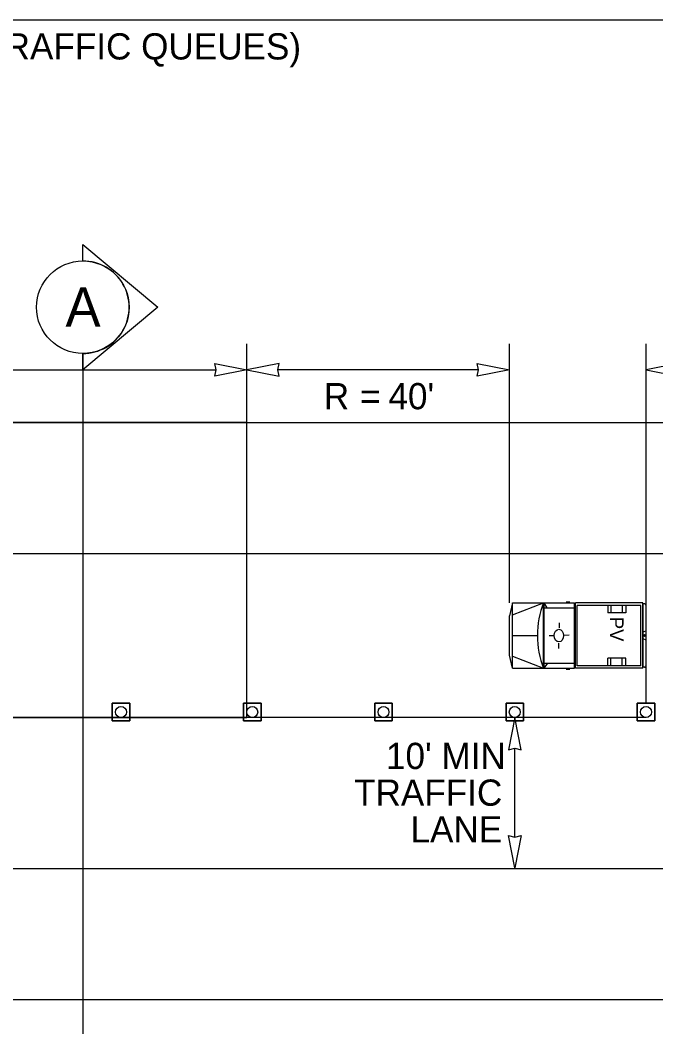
# Model space of a CAD drawing. Extents: x 99999.1 to 100095.7, y 99995 to 100010.7.
# Drawn here: x 100049.243 to 100051.18, y 100005.649 to 100008.719 of the extents above; entities that cross this region are included whole.
import ezdxf

# ---------------------------------------------------------------- set-up
doc = ezdxf.new("R2010")
doc.units = 0
for name, color, linetype in [('RD_ED_ShoulderPavedEdge', 7, 'Continuous'), ('RD_MK_LineEdgeWhite', 7, 'Continuous'), ('RD_MK_LineSkipCenter', 7, 'Continuous'), ('SH_TI_WZSectionCut', 7, 'Continuous'), ('TR_WZ_ProtectiveVehicle', 7, 'Continuous'), ('TR_WZ_TrafficCone', 7, 'Continuous'), ('TR_WZ_WorkZoneDetails', 7, 'Continuous'), ('TR_WZ_WorkZoneTextCurrent', 7, 'Continuous')]:
    doc.layers.add(name, color=color, linetype=linetype)

msp = doc.modelspace()

# ---------------------------------------------------------------- linework, layer by layer
at = {"layer": 'RD_ED_ShoulderPavedEdge'}
for p, q in [((100040.1076, 100007.4923), (100055.6424, 100007.4923)), ((100040.1076, 100005.7323), (100055.6424, 100005.7323))]:
    msp.add_line(p, q, dxfattribs=at)
at = {"layer": 'RD_MK_LineEdgeWhite'}
for p, q in [((100040.1076, 100007.0923), (100055.6424, 100007.0923)), ((100040.1076, 100006.1323), (100055.6424, 100006.1323))]:
    msp.add_line(p, q, dxfattribs=at)
at = {"layer": 'RD_MK_LineSkipCenter'}
msp.add_lwpolyline([(100051.15, 100006.5923), (100043.4767, 100006.5923)], dxfattribs=at)
at = {"layer": 'SH_TI_WZSectionCut'}
for p, q in [((100049.4337, 100007.9847), (100049.4337, 100008.0346)), ((100049.4337, 100008.0346), (100049.6619, 100007.8435)), ((100049.6619, 100007.8435), (100049.4337, 100007.6523)), ((100049.4337, 100007.6523), (100049.4337, 100007.7022)), ((100049.4338, 100007.7022), (100049.4338, 100005.5723))]:
    msp.add_line(p, q, dxfattribs=at)
msp.add_circle((100049.4338, 100007.8435), 0.1412, dxfattribs=at)
msp.add_arc((100049.4338, 100007.8435), 0.1412, 269.9978, 90.0022, dxfattribs=at)
at = {"layer": 'TR_WZ_ProtectiveVehicle'}
for p, q in [((100050.743, 100006.9423), (100050.7338, 100006.902)), ((100050.743, 100006.7423), (100050.743, 100006.9423)), ((100050.743, 100006.9423), (100050.9319, 100006.9423)), ((100050.743, 100006.9057), (100050.8375, 100006.9423)), ((100050.8375, 100006.7423), (100050.8375, 100006.9423)), ((100050.8392, 100006.7423), (100050.8392, 100006.9423)), ((100050.8492, 100006.9268), (100050.8392, 100006.9423)), ((100050.8392, 100006.9268), (100050.9319, 100006.9268)), ((100050.9062, 100006.9451), (100050.9175, 100006.9451)), ((100050.9319, 100006.7423), (100050.9319, 100006.9423)), ((100051.1404, 100006.9423), (100050.9347, 100006.9423)), ((100050.9347, 100006.7423), (100050.9347, 100006.9423)), ((100051.1346, 100006.9344), (100050.9405, 100006.9344)), ((100050.9405, 100006.7503), (100050.9405, 100006.9344)), ((100051.0332, 100006.9344), (100051.0332, 100006.9113)), ((100051.0432, 100006.9344), (100051.0432, 100006.9113)), ((100051.0772, 100006.9344), (100051.0772, 100006.9113)), ((100051.0882, 100006.9344), (100051.0882, 100006.9113)), ((100051.1346, 100006.7503), (100051.1346, 100006.9344)), ((100051.1404, 100006.7423), (100051.1404, 100006.9423)), ((100051.1456, 100006.939), (100051.1411, 100006.939)), ((100051.1411, 100006.7456), (100051.1411, 100006.939)), ((100051.15, 100006.7517), (100051.15, 100006.9329)), ((100050.7338, 100006.7827), (100050.7338, 100006.902)), ((100051.0882, 100006.9113), (100051.0332, 100006.9113)), ((100050.8852, 100006.8808), (100050.885, 100006.8658)), ((100050.743, 100006.8423), (100050.8189, 100006.8423)), ((100050.8544, 100006.8422), (100050.867, 100006.8423)), ((100050.8986, 100006.8427), (100050.8986, 100006.8427)), ((100050.9154, 100006.8431), (100050.9005, 100006.8427)), ((100051.15, 100006.8564), (100051.1411, 100006.8527)), ((100051.15, 100006.8282), (100051.1411, 100006.832)), ((100051.1476, 100006.8423), (100051.1435, 100006.8423)), ((100051.1456, 100006.8395), (100051.1456, 100006.8451)), ((100050.8845, 100006.8027), (100050.8845, 100006.8188)), ((100050.743, 100006.7423), (100050.7338, 100006.7827)), ((100050.743, 100006.779), (100050.8375, 100006.7423)), ((100051.0882, 100006.7733), (100051.0332, 100006.7733)), ((100051.0332, 100006.7503), (100051.0332, 100006.7733)), ((100051.0432, 100006.7503), (100051.0432, 100006.7733)), ((100051.0772, 100006.7503), (100051.0772, 100006.7733)), ((100051.0882, 100006.7503), (100051.0882, 100006.7733)), ((100050.743, 100006.7423), (100050.9319, 100006.7423)), ((100050.8392, 100006.7423), (100050.8512, 100006.7578)), ((100050.8392, 100006.7578), (100050.9319, 100006.7578)), ((100050.9062, 100006.7395), (100050.9175, 100006.7395)), ((100051.1404, 100006.7423), (100050.9347, 100006.7423)), ((100051.1346, 100006.7503), (100050.9405, 100006.7503)), ((100051.1456, 100006.7456), (100051.1411, 100006.7456))]:
    msp.add_line(p, q, dxfattribs=at)
for centre, major_axis, start_param, end_param in [((100050.9725, 100006.8424), (0, -0.2099), 4.215852, 5.209111), ((100051.1456, 100006.9329), (0, 0.0061), 4.712389, 6.283185), ((100051.1456, 100006.7517), (0, -0.0061), 6.283185, 7.853982)]:
    msp.add_ellipse(centre, major_axis=major_axis, ratio=0.73155, start_param=start_param, end_param=end_param, dxfattribs=at)
for centre, major_axis in [((100050.8845, 100006.8423), (0, 0.0193)), ((100051.1456, 100006.8423), (0, 0.00282))]:
    msp.add_ellipse(centre, major_axis=major_axis, ratio=0.73155, dxfattribs=at)
at = {"layer": 'TR_WZ_TrafficCone'}
for points in [[(100049.5234, 100006.6357), (100049.5767, 100006.6357), (100049.5767, 100006.5823), (100049.5234, 100006.5823), (100049.5234, 100006.6357)], [(100049.5234, 100006.5823), (100049.5767, 100006.5823), (100049.5767, 100006.6357), (100049.5234, 100006.6357), (100049.5234, 100006.5823)], [(100049.9234, 100006.6357), (100049.9767, 100006.6357), (100049.9767, 100006.5823), (100049.9234, 100006.5823), (100049.9234, 100006.6357)], [(100049.9234, 100006.5823), (100049.9767, 100006.5823), (100049.9767, 100006.6357), (100049.9234, 100006.6357), (100049.9234, 100006.5823)], [(100050.3234, 100006.6357), (100050.3767, 100006.6357), (100050.3767, 100006.5823), (100050.3234, 100006.5823), (100050.3234, 100006.6357)], [(100050.3234, 100006.5823), (100050.3767, 100006.5823), (100050.3767, 100006.6357), (100050.3234, 100006.6357), (100050.3234, 100006.5823)], [(100050.7234, 100006.6357), (100050.7767, 100006.6357), (100050.7767, 100006.5823), (100050.7234, 100006.5823), (100050.7234, 100006.6357)], [(100050.7234, 100006.5823), (100050.7767, 100006.5823), (100050.7767, 100006.6357), (100050.7234, 100006.6357), (100050.7234, 100006.5823)], [(100051.1766, 100006.6357), (100051.1233, 100006.6357), (100051.1233, 100006.5823), (100051.1766, 100006.5823), (100051.1766, 100006.6357)], [(100051.1766, 100006.5823), (100051.1233, 100006.5823), (100051.1233, 100006.6357), (100051.1766, 100006.6357), (100051.1766, 100006.5823)]]:
    msp.add_lwpolyline(points, dxfattribs=at)
for centre in [(100049.55, 100006.609), (100049.95, 100006.609), (100050.35, 100006.609), (100050.75, 100006.609), (100051.15, 100006.609)]:
    msp.add_circle(centre, 0.0167, dxfattribs=at)
at = {"layer": 'TR_WZ_WorkZoneDetails'}
for p, q in [((100051.3796, 100008.7191), (100044.3704, 100008.7191)), ((100049.9338, 100007.4923), (100049.9338, 100007.7323)), ((100050.7338, 100006.9423), (100050.7338, 100007.7323)), ((100051.15, 100006.6357), (100051.15, 100007.7323)), ((100045.2437, 100007.6523), (100049.84, 100007.6523)), ((100050.64, 100007.6523), (100050.0275, 100007.6523)), ((100050.75, 100006.2278), (100050.75, 100006.4986))]:
    msp.add_line(p, q, dxfattribs=at)
for points in [[(100049.9338, 100007.6523), (100049.8355, 100007.6331), (100049.84, 100007.6523), (100049.8355, 100007.6716)], [(100049.9338, 100007.6523), (100050.032, 100007.6331), (100050.0275, 100007.6523), (100050.032, 100007.6716)], [(100050.7338, 100007.6523), (100050.6355, 100007.6331), (100050.64, 100007.6523), (100050.6355, 100007.6716)], [(100051.15, 100007.6523), (100051.2483, 100007.6331), (100051.2437, 100007.6523), (100051.2483, 100007.6716)], [(100045.15, 100007.4923), (100045.15, 100006.5923), (100049.9338, 100006.5923), (100049.9338, 100007.4923)], [(100050.75, 100006.5923), (100050.7308, 100006.4941), (100050.75, 100006.4986), (100050.7693, 100006.4941)], [(100050.75, 100006.1341), (100050.7308, 100006.2324), (100050.75, 100006.2278), (100050.7693, 100006.2324)]]:
    msp.add_lwpolyline(points, close=True, dxfattribs=at)

# ---------------------------------------------------------------- texts
at = {"layer": 'SH_TI_WZSectionCut'}
msp.add_text('A', height=0.12, rotation=359.99, dxfattribs=at).set_placement((100049.3808, 100007.7843))
at = {"layer": 'TR_WZ_ProtectiveVehicle'}
msp.add_text('PV', height=0.04175, rotation=270, dxfattribs=at).set_placement((100051.0398, 100006.899))
at = {"layer": 'TR_WZ_WorkZoneTextCurrent'}
for s, p in [('(MINIMIZE DISTANCE BETWEEN MAINLINE FLAGGERS TO MINIMIZE DELAYS & TRAFFIC QUEUES)', (100045.0644, 100008.5991)), ('R', (100050.1681, 100007.5323)), ("40'", (100050.365, 100007.5323)), ('=', (100050.2786, 100007.5323)), ("10' MIN", (100050.3575, 100006.4352)), ('TRAFFIC', (100050.2604, 100006.3232)), ('LANE', (100050.4323, 100006.2112))]:
    msp.add_text(s, height=0.08, dxfattribs=at).set_placement(p)

doc.saveas('drawing.dxf')
